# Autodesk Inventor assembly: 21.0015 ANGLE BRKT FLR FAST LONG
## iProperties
Created: 2012-08
Part Number: 21.0015 ANGLE BRKT FLR FAST LONG
Document SubType Name: Assembly
Designer: Administrator
Author: Administrator
